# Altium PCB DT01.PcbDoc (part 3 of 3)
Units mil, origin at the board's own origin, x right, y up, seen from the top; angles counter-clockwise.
Board outline 2134.7 x 2226.1 mil, 2 copper layers (Top Layer, Bottom Layer), stack 57.918 mil thick; 95 components, 87 nets, 468 pads, 300 vias.
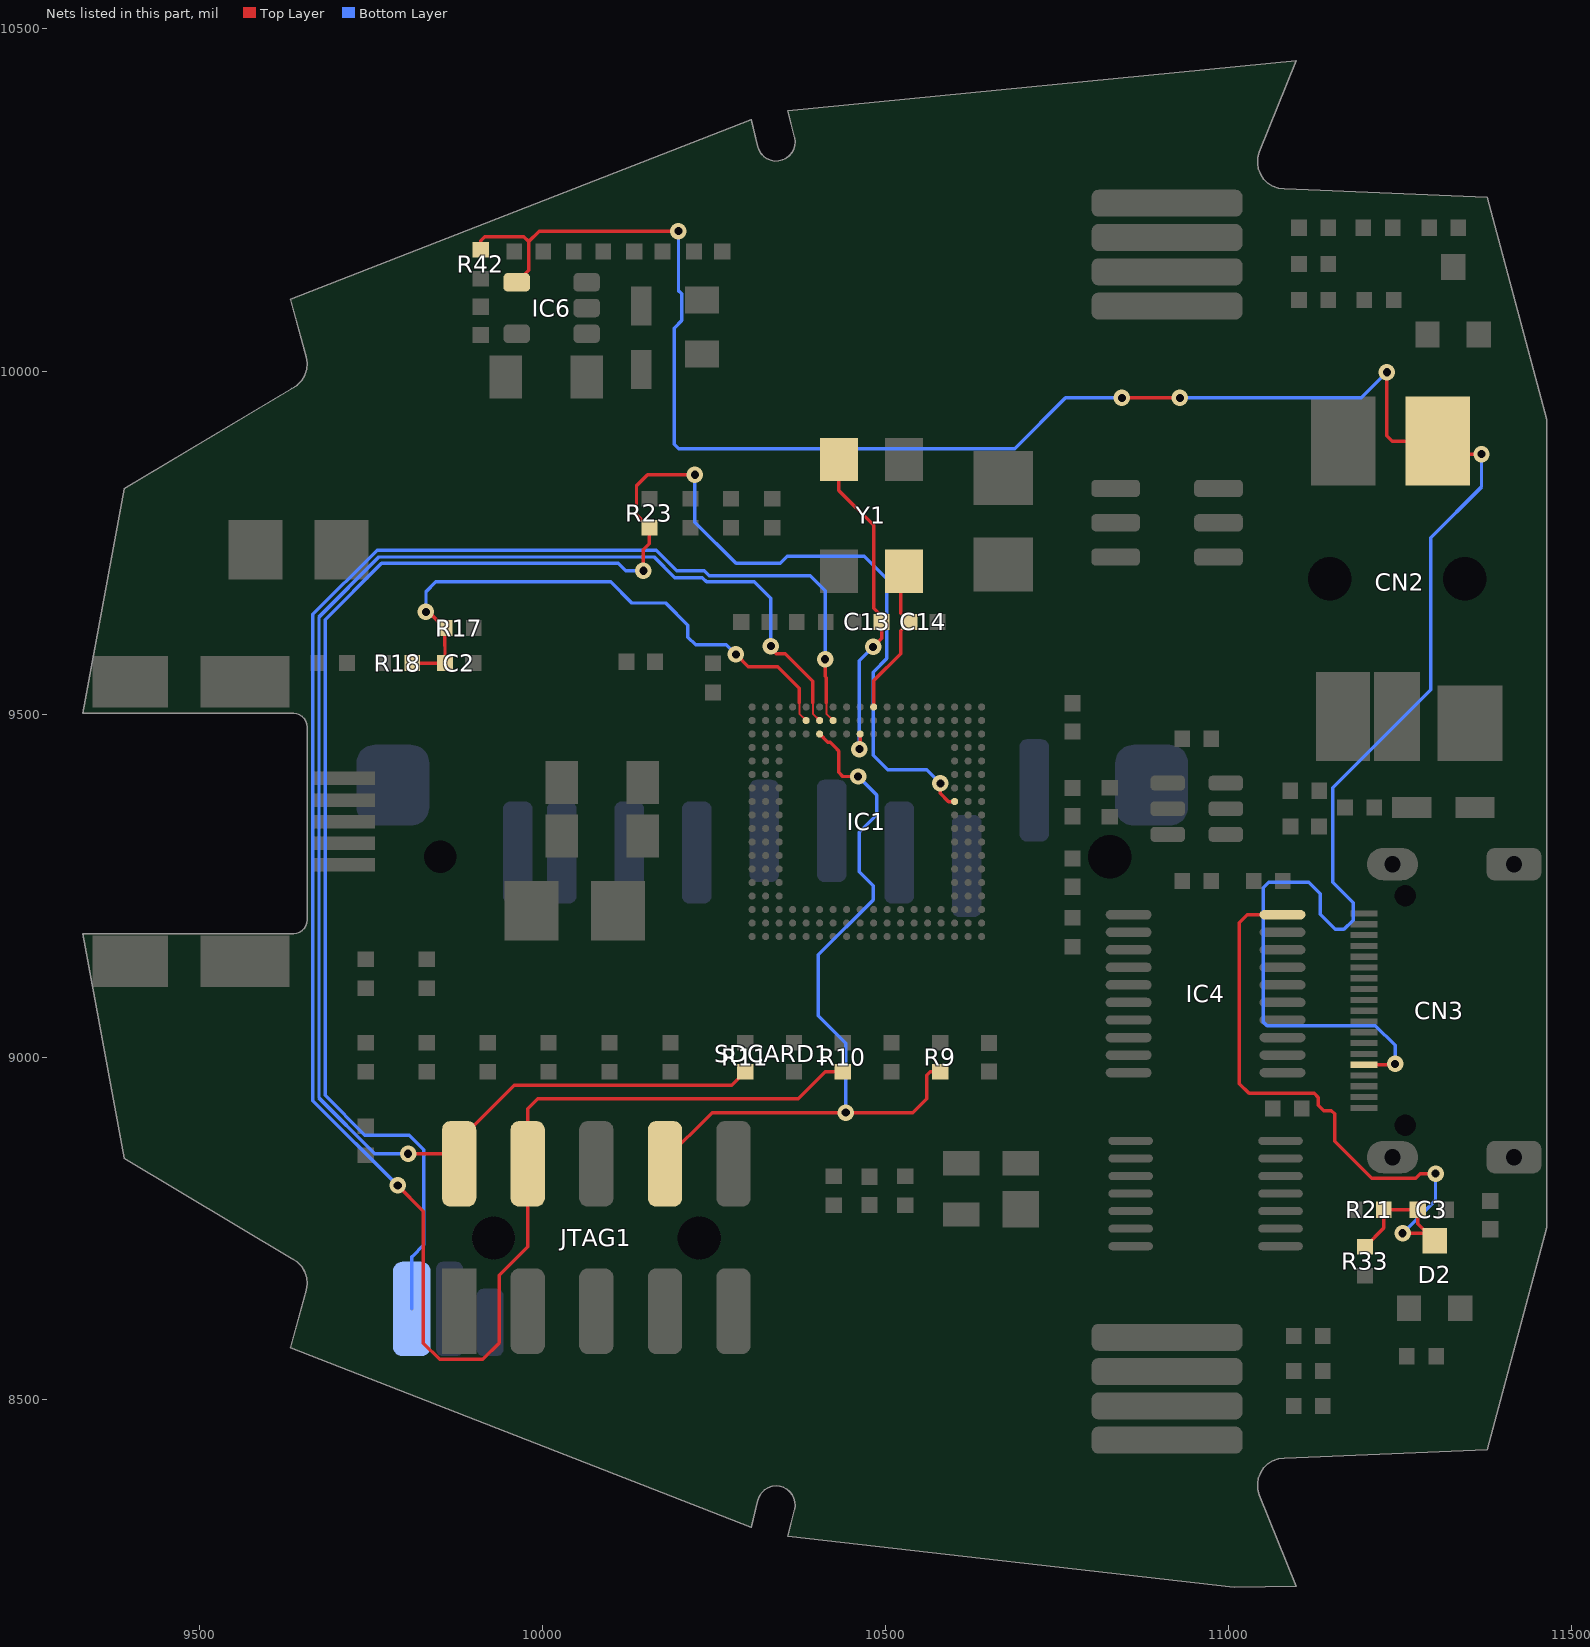
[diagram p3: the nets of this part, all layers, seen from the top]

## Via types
v1: diameter 24, hole 11.81, Top Layer to Bottom Layer, tented both sides, 295 vias
v2: diameter 24.02, hole 11.81, Top Layer to Bottom Layer, tented both sides, 5 vias

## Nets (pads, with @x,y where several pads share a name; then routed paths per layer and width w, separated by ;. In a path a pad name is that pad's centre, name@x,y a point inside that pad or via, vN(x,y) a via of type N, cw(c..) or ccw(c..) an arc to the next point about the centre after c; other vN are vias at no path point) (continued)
TDO: IC1.U13 JTAG1.2 R11.1 | length 2361.9
  Top Layer w3: 10394.06,9516.79 10394.06,9500.5 IC1.U13@10403.95,9490.61
  Top Layer w5: v1(9804.01,8859.02) JTAG1.2@9873.01,8859.02 ; JTAG1.2@9878.38,8844.21 9878.38,8878.67 9958.73,8959.02 10276.11,8959.02 R11.1@10295.6,8978.5 R11.1@10293.01,8978.5 ; v1@10333.01,9596.02 10341.01,9588.02 10354.01,9588.02 10394.06,9547.97 10394.06,9516.79
  Bottom Layer w5: v1(9804.01,8859.02) 9755.25,8859.02 9674,8940.26 9674,9641.59 9761.43,9729.02 10163.01,9729.02 10193.01,9699.02 10233.01,9699.02 10239.02,9693 10308.77,9693 10333.01,9668.76 v1(10333.01,9599.02)
TMS: IC1.U12 JTAG1.4 R10.1 | length 3104.8
  Top Layer w3: 10413.74,9516.79 10413.74,9500.5 IC1.U12@10423.63,9490.61
  Top Layer w5: v1(9788.83,8812.7) 9826.22,8775.31 9826.22,8582.63 9849.84,8559.02 9913.01,8559.02 9937.01,8583.02 9937.01,8682.02 9978.38,8723.4 JTAG1.4@9978.38,8844.21 9978.38,8924.4 9993.01,8939.02 10373.01,8939.02 10412.49,8978.5 R10.1@10437.79,8978.5 ; v1(10412.01,9580.02) 10412.01,9554.87 10413.74,9553.13 10413.74,9516.79
  Bottom Layer w5: v1(9788.83,8812.7) 9665,8936.54 9665,9645.32 9758.7,9739.02 10165.73,9739.02 10195.73,9709.02 10235.73,9709.02 10242.75,9702 10390.02,9702 10412.01,9680.02 v1(10412.01,9580.02)
TPS: C3.1 D2.3 IC4.20 R21.1 R33.1 | length 991.2
  Top Layer w5: IC4.20@11078.92,9207.48 11027.48,9207.48 11016,9196 11016,8961 11030,8947 11125,8947 11131,8941 11131,8929.65 11139,8921.65 11150.22,8921.65 11154.88,8917 11154.88,8877.12 11208.92,8823.08 11273,8823.08 11279.92,8830 v1(11302,8830) ; R33.1@11199.29,8723.57 11226.37,8750.66 R21.1@11226.37,8777.18 C3.1@11276.03,8777.18 11276.03,8756.71 D2.3@11289.75,8743 ; v1(11254,8743) D2.3@11289.75,8743 ; D2.3@11300.73,8732.02 D2.3@11289.75,8743
  Bottom Layer w5: v1(11254,8743) 11302,8791 v1(11302,8830)
TRST: IC1.T13 JTAG1.8 R9.1 | length 1153.3
  Top Layer w5: JTAG1.8@10178.38,8844.21 10178.38,8850.18 10247.22,8919.02 v1(10442.01,8919.02) 10540.01,8919.02 10560.01,8939.02 10560.01,8973.5 10565.01,8978.5 R9.1@10579.97,8978.5 ; IC1.T13@10403.01,9469.02 10403.95,9469.02 IC1.T13@10403.95,9470.92 10415.85,9459.02 10419.17,9459.02 10425.19,9453 10432.01,9446.18 10432.01,9437.02 10432,9415 10437.98,9409.02 v1(10460.01,9409.02)
  Bottom Layer w5: v1(10442.01,8919.02) 10442.01,9020.29 10402.01,9060.29 10402.01,9148.94 10482.01,9228.94 10482.01,9250.02 10462.01,9270.02 10462.01,9328.02 10487.01,9353.02 10487.01,9382.02 v1(10460.01,9409.02)
VPP_ON: CN2.4 CN3.15 IC6.4 R42.2 | length 3470.2
  Top Layer w5: R42.2@9910.37,10177.07 R42.2@9909.87,10177.06 9909.87,10190.31 9915.77,10196.21 9972.82,10196.21 9980.01,10189.02 ; IC6.4@9962.36,10129.53 9980.01,10147.18 9980.01,10189.02 ; v1(10198.18,10204.22) 9995.21,10204.22 9980.01,10189.02 ; v1(10844.66,9961.03) v1(10929.29,9961.03) ; CN3.15@11197.86,8988.84 11227.01,8988.84 11227.01,8989.02 11242.01,8989.02 v1(11243.01,8990.02) ; v1(11231.01,9998.42) 11231.01,9905.93 11238.81,9898.13 CN2.4@11305.14,9898.13 11324.25,9879.02 v1(11369.01,9879.02)
  Bottom Layer w5: v1(10198.18,10204.22) 10198.18,10117.49 10203.1,10112.57 10203.1,10073.9 10192.01,10062.81 10192.01,9893.34 10198.33,9887.02 10688.42,9887.02 10762.43,9961.03 v1(10844.66,9961.03) ; v1(10929.29,9961.03) 11193.61,9961.03 v1(11231.01,9998.42) ; v1(11243.01,8990.02) 11243.01,9016.93 11214.16,9045.77 11056.23,9045.77 11051,9051 11051,9247 11059,9255 11117,9255 11134,9238 11134,9208 11156,9186 11168.59,9186 11182.01,9199.42 11182.01,9225 11152.01,9255 11152.01,9392.56 11295.19,9535.75 11295.19,9757.32 11369.01,9831.14 v1(11369.01,9879.02)
VUSB: C2.2 IC1.U14 R17.1 R18.1 | length 841.7
  Top Layer w3: 10374.37,9516.79 10374.37,9500.5 IC1.U14@10384.26,9490.61
  Top Layer w5: R18.1@9810.02,9574.34 C2.2@9857.71,9574.34 9857.71,9599.02 9857.2,9599.53 R17.1@9857.2,9625.51 9833.69,9649.02 v1(9830.01,9649.02) ; v1(10282.01,9587.02) 10300.01,9569.02 10343.01,9569.02 10374.37,9537.65 10374.37,9516.79
  Bottom Layer w5: v1(9830.01,9649.02) 9830.01,9678.47 9844.55,9693.02 10099.24,9693.02 10130.24,9662.02 10179.67,9662.02 10212,9629.69 10212,9612 10223.11,9600.89 10268.14,9600.89 v1(10282.01,9587.02)
WP_DET: IC1.L3 R23.1 SDCARD1.SW2 | length 2652.9
  Top Layer w5: v1(10147.01,9709.02) 10147.01,9739.63 10155.87,9748.5 R23.1@10155.87,9771.61 10137.01,9790.47 10137.01,9833.02 10153.01,9849.02 v1(10222.01,9849.02) ; v1(10580.01,9399.02) 10580.01,9384.37 10591.88,9372.5 IC1.L3@10600.8,9372.5
  Bottom Layer w5: SDCARD1.SW2@9809.33,8632.63 9809.33,8709.02 9810.01,8709.02 9827.01,8726.02 9827.01,8865.02 9805.86,8886.17 9740.83,8886.17 9683,8943.99 9683,9637.86 9765.15,9720.02 10110.42,9720.02 10121.42,9709.02 v1(10147.01,9709.02) ; v1(10222.01,9849.02) 10222.01,9780.02 10282.02,9720 10346.59,9720 10356.61,9730.02 10469.28,9730.02 10502.01,9697.29 10502.01,9581.02 10482.01,9561.02 10482.01,9440.02 10503.01,9419.02 10560.01,9419.02 v1(10580.01,9399.02)
XTALI: C13.1 IC1.T10 Y1.1 | length 486.5
  Top Layer w5: Y1.1@10432.11,9869.02 Y1.1@10432.1,9871.33 10432.1,9825.96 10483.01,9775.06 10483.01,9654.36 C13.1@10498.69,9638.68 ; v1(10462.01,9449.02) 10462.01,9457.22 10463,9458.22 IC1.T10@10463,9469.02 ; IC1.T10@10462.01,9469.02 IC1.T10@10463,9469.02 ; v1(10482.01,9598.02) 10494.37,9610.38 C13.1@10494.37,9634.36 ; IC1.T10@10463,9469.02 IC1.T10@10463,9470.92 IC1.T10@10463,9469.02
  Bottom Layer w5: v1(10462.01,9449.02) 10462.01,9578.02 v1(10482.01,9598.02)
XTALO: C14.1 IC1.V9 Y1.3 | length 223.8
  Top Layer w5: IC1.V9@10482.69,9510.29 10483.01,9510.29 10483.01,9549.02 10522.01,9588.02 10522.01,9621.66 C14.1@10534.7,9634.36 ; Y1.3@10527.1,9708.33 10526.42,9708.33 10522.01,9703.92 10522.01,9647.04 C14.1@10532.02,9637.03
pads on no net: CN2.MH1 CN2.MH2 CN3.16 CN3.17 CN3.19 CN3.MH5 CN3.MH6 D1.3 IC1.A8 IC1.A9 IC1.A10 IC1.A11 IC1.A12 IC1.A13 IC1.A14 IC1.A17 IC1.A18 IC1.B3 IC1.B9 IC1.B10 IC1.B11 IC1.B12 IC1.B13 IC1.B14 IC1.B15 IC1.B16 IC1.B17 IC1.B18 IC1.C1 IC1.C2 IC1.C3 IC1.C9 IC1.C10 IC1.C11 IC1.C12 IC1.C13 IC1.C14 IC1.C15 IC1.C16 IC1.C17 IC1.C18 IC1.D1 IC1.D2 IC1.D3 IC1.D16 IC1.D17 IC1.D18 IC1.E2 IC1.E3 IC1.E16 IC1.E17 IC1.E18 IC1.F2 IC1.F3 IC1.F16 IC1.F17 IC1.F18 IC1.G2 IC1.G16 IC1.G17 IC1.G18 IC1.H17 IC1.K1 IC1.K2 IC1.K16 IC1.K17 IC1.L2 IC1.M1 IC1.M2 IC1.M3 IC1.N1 IC1.N2 IC1.N3 IC1.P3 IC1.R3 IC1.T1 IC1.T2 IC1.T3 IC1.T4 IC1.T6 IC1.T7 IC1.T8 IC1.U1 IC1.U2 IC1.U5 IC1.U6 IC1.U7 IC1.V1 IC2.3 IC2.5 IC2.6 SDCARD1.MH3 SDCARD1.MH4
copper on no net: | length 12322.3
  Top Layer w5: 13672.98,13929.05 13672.98,14024.05 14592.98,14024.05 14592.98,13929.05 13672.98,13929.05
  Top Layer w10: 6107.15,10595.13 6107.15,11057.18 6817.15,11057.18 6817.15,10595.13 6107.15,10595.13
  Top Layer w40: 10738.55,8378.48 10508.24,8378.48 cw(c10508.24,8516.27) 10508.24,8654.07 10738.55,8654.07 ; 10738.55,10032.02 10508.24,10032.02 cw(c10508.24,10169.82) 10508.24,10307.61 10738.55,10307.61
  Bottom Layer w5: 13672.98,13834.05 13672.98,13929.05 14592.98,13929.05 14592.98,13834.05 13672.98,13834.05
  Bottom Layer w10: 6107.15,10595.13 6107.15,11057.18 6817.15,11057.18 6817.15,10595.13 6107.15,10595.13
  Bottom Layer w40: 10738.55,8378.48 10508.24,8378.48 cw(c10508.24,8516.27) 10508.24,8654.07 10738.55,8654.07 ; 10738.55,10032.02 10508.24,10032.02 cw(c10508.24,10169.82) 10508.24,10307.61 10738.55,10307.61
  other v2: 10830.98,9882.99 10932.01,9882.99 10820,10045 11197.01,10052.99

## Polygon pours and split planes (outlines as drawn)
GND on Top Layer "TOPGND" (solid, remove dead copper, pour order 1000): 11097.83,8230.7 11044.32,8363.83 11042.45,8378.76 11053.27,8408.28 11080.68,8417.88 11228.42,8421.07 11376.58,8429.84 11425.22,8590.32 11463.13,8754.11 11463.13,9931.98 11432.11,10071.24 11376.58,10256.24 11226.46,10265.09 11080.68,10268.2 11065.08,10270.99 11053.27,10278.86 11043.43,10293.62 11041.46,10307.4 11044.32,10322.26 11097.83,10455.38 10842.7,10453.03 10592.76,10426.46 10471.73,10405.8 10356.73,10382.38 10366.39,10343.02 10367.42,10331.02 10364.47,10323.14 10352.66,10311.34 10335.94,10308.38 10319.21,10317.24 10312.86,10329.88 10303.15,10369.43 10081.08,10304.45 9861.65,10218.84 9631.51,10107.14 9654.65,10023.4 9656.98,10015.15 9655.01,10003.34 9650.09,9989.57 9633.7,9977.41 9512.33,9916.75 9388.86,9831.12 9351.94,9676.66 9328.42,9503.48 9636.2,9503.48 9654.02,9489.7 9655.89,9202.3 9636.2,9182.61 9328.42,9182.61 9349.97,9017.38 9388.86,8854.97 9510.36,8775.31 9633.7,8708.68 9644.18,8701.51 9651.07,8693.64 9655.01,8683.8 9655.99,8674.94 9654.65,8662.69 9631.51,8578.94 9799.66,8493.89 9916.75,8444.69 10041.72,8394.5 10250.33,8329.56 10303.15,8316.66 10312.86,8356.21 10317.24,8364.98 10321.18,8370.89 10329.05,8375.81 10335.94,8377.78 10344.79,8376.79 10351.68,8374.82 10359.55,8369.9 10362.5,8365.97 10366.44,8359.08 10367.42,8352.19 10366.39,8343.07 10356.73,8303.7 10547.5,8266.58 10673.45,8248.87 10751.18,8241 10825.97,8235.1 10899.77,8231.16 10941.1,8230.18 11009.98,8230.18 11023.75,8229.19 11036.54,8230.18 11062.13,8231.16
GND on Bottom Layer "BOTGND" (solid, remove dead copper, pour order 1001): 11097.83,8230.7 11044.32,8363.83 11042.45,8378.76 11053.27,8408.28 11080.68,8417.88 11228.42,8421.07 11376.58,8429.84 11425.22,8590.32 11463.13,8754.11 11463.13,9931.98 11432.11,10071.24 11376.58,10256.24 11226.46,10265.09 11080.68,10268.2 11065.08,10270.99 11053.27,10278.86 11043.43,10293.62 11041.46,10307.4 11044.32,10322.26 11097.83,10455.38 10842.7,10453.03 10592.76,10426.46 10471.73,10405.8 10356.73,10382.38 10366.39,10343.02 10367.42,10331.02 10364.47,10323.14 10352.66,10311.34 10335.94,10308.38 10319.21,10317.24 10312.86,10329.88 10303.15,10369.43 10081.08,10304.45 9861.65,10218.84 9631.51,10107.14 9654.65,10023.4 9656.98,10015.15 9655.01,10003.34 9650.09,9989.57 9633.7,9977.41 9512.33,9916.75 9388.86,9831.12 9351.94,9676.66 9328.42,9503.48 9636.2,9503.48 9654.02,9489.7 9655.89,9202.3 9636.2,9182.61 9328.42,9182.61 9349.97,9017.38 9388.86,8854.97 9510.36,8775.31 9633.7,8708.68 9644.18,8701.51 9651.07,8693.64 9655.01,8683.8 9655.99,8674.94 9654.65,8662.69 9631.51,8578.94 9799.66,8493.89 9916.75,8444.69 10041.72,8394.5 10250.33,8329.56 10303.15,8316.66 10312.86,8356.21 10317.24,8364.98 10321.18,8370.89 10329.05,8375.81 10335.94,8377.78 10344.79,8376.79 10351.68,8374.82 10359.55,8369.9 10362.5,8365.97 10366.44,8359.08 10367.42,8352.19 10366.39,8343.07 10356.73,8303.7 10547.5,8266.58 10673.45,8248.87 10751.18,8241 10825.97,8235.1 10899.77,8231.16 10941.1,8230.18 11009.98,8230.18 11023.75,8229.19 11036.54,8230.18 11062.13,8231.16
no net on Keep-Out Layer (solid): 10738.55,10307.61 10509.06,10307.61 10499.2,10307.5 10488.4,10306.4 10481.5,10304.7 10474.7,10303.5 10463.7,10300.3 10451.3,10295.4 10441.4,10290.7 10428.3,10281.8 10417.61,10273.94 10409.1,10265.8 10401.9,10257.4 10394,10246.7 10387.3,10235.4 10381,10222.8 10377,10211.8 10372.8,10195.3 10371.4,10183.9 10370.5,10172.6 10371.1,10154.4 10374,10138.3 10377,10126.7 10382.5,10113.2 10387.9,10102.9 10398.5,10085.8 10412.3,10070.8 10426.5,10059.1 10435.2,10052.9 10446.7,10046.5 10463.6,10039.5 10473.8,10036.5 10487,10033.6 10491.9,10033 10495.4,10032.6 10501.1,10032.1 10508.24,10032.02 10738.55,10032.02 10741.1,10032.2 10743,10032.5 10745.4,10033.3 10747.1,10034 10748.8,10034.9 10750.3,10035.8 10751.2,10036.8 10752.5,10037.8 10754.6,10040.3 10756,10042.3 10757.1,10045 10757.8,10047.6 10758.2,10050 10758.24,10051.71 10758.24,10287.93 10757.8,10291.7 10757.2,10294.6 10755.4,10298.3 10753.15,10301.5 10750.9,10303.5 10748,10305.2 10744,10307
no net on Keep-Out Layer (solid): 10738.55,8654.07 10509.06,8654.07 10499.2,8653.96 10488.4,8652.86 10481.5,8651.16 10474.7,8649.96 10463.7,8646.76 10451.3,8641.86 10441.4,8637.16 10428.3,8628.26 10417.61,8620.4 10409.1,8612.26 10401.9,8603.86 10394,8593.16 10387.3,8581.86 10381,8569.26 10377,8558.26 10372.8,8541.76 10371.4,8530.36 10370.5,8519.06 10371.1,8500.86 10374,8484.76 10377,8473.16 10382.5,8459.66 10387.9,8449.36 10398.5,8432.26 10412.3,8417.26 10426.5,8405.56 10435.2,8399.36 10446.7,8392.96 10463.6,8385.96 10473.8,8382.96 10487,8380.06 10491.9,8379.46 10495.4,8379.06 10501.1,8378.56 10508.24,8378.48 10738.55,8378.48 10741.1,8378.66 10743,8378.96 10745.4,8379.76 10747.1,8380.46 10748.8,8381.36 10750.3,8382.26 10751.2,8383.26 10752.5,8384.26 10754.6,8386.76 10756,8388.76 10757.1,8391.46 10757.8,8394.06 10758.2,8396.46 10758.24,8398.16 10758.24,8634.38 10757.8,8638.16 10757.2,8641.06 10755.4,8644.76 10753.15,8647.95 10750.9,8649.96 10748,8651.66 10744,8653.46

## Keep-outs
Keep-Out Layer:
  rectangle: 13672.98,12418.05 13862.98,12513.05
  lines w5: 13672.98,12418.05 13672.98,12513.05 14592.98,12513.05 14592.98,12418.05 13672.98,12418.05
  text "ROUTING KEEPOUT LAYER" at 13932.98,12445.05 h35

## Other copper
Top Layer:
  rectangle net 5V0: 9708,9252 9732,9285
  rectangle: 13672.98,13929.05 13862.98,14024.05
  pour cut-out: 10305.52,9510.29 10640.17,9510.29 10640.17,9175.65 10305.52,9175.65
  text "TOP LAYER" at 13932.98,13956.05 h40
  text "LAYER" at 6337.58,10910.08 h60
  text "TOP" at 6310.02,10701.42 h120
Bottom Layer:
  rectangle: 13672.98,13834.05 13862.98,13929.05
  text "BOTTOM LAYER" at 13932.98,13861.05 h40
  text "LAYER" at 6337.58,10910.08 h60
  text "BOTTOM" at 6148.6,10705.35 h120
Multi-Layer:
  rectangle: 13672.98,13008.05 13862.98,13103.05
  lines w5: 13672.98,13008.05 13672.98,13103.05 14592.98,13103.05 14592.98,13008.05 13672.98,13008.05
  text "MULTILAYER" at 13932.98,13035.05 h40
  text "OF" at 22030.96,501.86 h80
  text "1" at 21835.88,501.31 h120
  text "1" at 22270.88,501.31 h120

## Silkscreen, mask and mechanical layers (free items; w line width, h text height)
Top Overlay:
  drawing of 466 lines, arcs and shapes, not listed
  text "TOP OVERLAY" at 13932.98,14192.05 h40
  text "K" at 10300.56,10129.75 h30
  text "FLAT" at 10898,10013 h40
  text "+" at 9767,9803 h80
  text "DS2406" at 10916.8,9722.6 h35 r90
  text "+" at 10739,9615 h80
  text "STX-2550-5N" at 11105.91,9609.87 h35 r90
  text "K" at 11401,9350 h30
  text "LPC288x" at 10260,9263 h40 r90
  text "+" at 9889,9100 h80
  text "74CBT3345" at 10992.76,8974.48 h28 r90
  text "INTERFACE" at 11368,8946 h50 r90
  text "G3168-05000102-00" at 11414.8,8927.2 h35 r90
  text "TARGET JTAG" at 11321.57,8915.39 h50 r90
  text "HC04" at 10996,8736 h34 r90
  text "FLAT" at 10877,8360 h40
Bottom Overlay:
  drawing of 1101 lines, arcs and shapes, not listed
  text "BOTTOM LEGEND" at 13932.98,13625.05 h40
  text "SD CARD" at 10491,9902 h80
  text "MANUFACTURE DATE:" at 11291,9740 h28 r90
  text "REVISION No:" at 10588,9732.29 h50
  text "DT01.02" at 11198,9655 h60 r90
  text "SVN 7266" at 10591,9640.36 h95
  text "MACHINE ID:" at 10588,9542.58 h50
  text ".ComputerName" at 10591,9453 h95
  text "DT01.02" at 11369.67,9244.43 h90 r90
  text "Developer" at 11426.67,9244.43 h60 r90
  text "Tool" at 11491.67,9244.43 h60 r90
  text "AD BUILD No:" at 10588,9109.58 h50
  text "COMPLIANCE" at 9755.08,9029.05 h52
  text ".Application_BuildNumber" at 10591,9020 h95
  text "IPC-A-600G" at 9712.08,8961.05 h30
  text "IPC-6012D" at 9712.08,8903.05 h30
Top Paste:
  rectangle: 13672.98,14283.05 13862.98,14378.05
  lines w5: 13672.98,14283.05 13672.98,14378.05 14592.98,14378.05 14592.98,14283.05 13672.98,14283.05
  text "TOP PASTE" at 13932.98,14310.05 h40
Bottom Paste:
  rectangle: 13672.98,13480.05 13862.98,13575.05
  lines w5: 13672.98,13480.05 13672.98,13575.05 14592.98,13575.05 14592.98,13480.05 13672.98,13480.05
  text "BOTTOM PASTE" at 13932.98,13507.05 h40
Top Solder:
  rectangle: 13672.98,14047.05 13862.98,14142.05
  lines w5: 13672.98,14047.05 14592.98,14047.05 14592.98,14142.05 13672.98,14142.05 13672.98,14047.05
  lines w40: 10738.55,8378.48 10508.24,8378.48 cw(c10508.24,8516.27) 10508.24,8654.07 10738.55,8654.07 ; 10738.55,10032.02 10508.24,10032.02 cw(c10508.24,10169.82) 10508.24,10307.61 10738.55,10307.61
  lines w60: 9622,9182.61 9366.52,9182.61 9328.42,9182.61 ccw(c11116.51,9343.04) 9388.86,8854.97 ccw(c10303.51,10107.8) 9633.7,8708.68 cw(c9616.7,8673.17) 9654.65,8662.69 9631.51,8578.94 ccw(c11007.41,11111.18) 10303.15,8316.66 10312.86,8356.21 cw(c10339.63,8349.64) 10366.39,8343.07 10356.73,8303.7 ccw(c11007.41,11111.18) 11097.83,8230.7 11044.32,8363.83 cw(c11080.85,8378.51) 11080.68,8417.88 ccw(c11063.75,12502.73) 11376.58,8429.84 ccw(c8605.87,9343.04) 11463.13,8754.11 11463.13,9287.93 11463.13,9520.21 11463.13,9697.37 11463.13,9931.98 ccw(c8605.87,9343.04) 11376.58,10256.24 ccw(c11063.75,6183.36) 11080.68,10268.2 cw(c11080.85,10307.57) 11044.32,10322.26 11097.83,10455.38 ccw(c11007.41,7574.91) 10356.73,10382.38 10366.39,10343.02 cw(c10339.63,10336.45) 10312.86,10329.88 10303.15,10369.43 ccw(c11007.41,7574.91) 9631.51,10107.14 9654.65,10023.4 cw(c9616.7,10012.92) 9633.7,9977.41 ccw(c10303.51,8578.29) 9388.86,9831.12 ccw(c11116.51,9343.04) 9328.42,9503.48 9366.52,9503.48 9622,9503.48
  text "TOP SOLDER MASK" at 13932.98,14074.05 h40
Bottom Solder:
  rectangle: 13672.98,13716.05 13862.98,13811.05
  lines w5: 13672.98,13716.05 13672.98,13811.05 14592.98,13811.05 14592.98,13716.05 13672.98,13716.05
  lines w40: 10738.55,8378.48 10508.24,8378.48 cw(c10508.24,8516.27) 10508.24,8654.07 10738.55,8654.07 ; 10738.55,10032.02 10508.24,10032.02 cw(c10508.24,10169.82) 10508.24,10307.61 10738.55,10307.61
  lines w60: 9622,9182.61 9366.52,9182.61 9328.42,9182.61 ccw(c11116.51,9343.04) 9388.86,8854.97 ccw(c10303.51,10107.8) 9633.7,8708.68 cw(c9616.7,8673.17) 9654.65,8662.69 9631.51,8578.94 ccw(c11007.41,11111.18) 10303.15,8316.66 10312.86,8356.21 cw(c10339.63,8349.64) 10366.39,8343.07 10356.73,8303.7 ccw(c11007.41,11111.18) 11097.83,8230.7 11044.32,8363.83 cw(c11080.85,8378.51) 11080.68,8417.88 ccw(c11063.75,12502.73) 11376.58,8429.84 ccw(c8605.87,9343.04) 11463.13,8754.11 11463.13,9287.93 11463.13,9520.21 11463.13,9697.37 11463.13,9931.98 ccw(c8605.87,9343.04) 11376.58,10256.24 ccw(c11063.75,6183.36) 11080.68,10268.2 cw(c11080.85,10307.57) 11044.32,10322.26 11097.83,10455.38 ccw(c11007.41,7574.91) 10356.73,10382.38 10366.39,10343.02 cw(c10339.63,10336.45) 10312.86,10329.88 10303.15,10369.43 ccw(c11007.41,7574.91) 9631.51,10107.14 9654.65,10023.4 cw(c9616.7,10012.92) 9633.7,9977.41 ccw(c10303.51,8578.29) 9388.86,9831.12 ccw(c11116.51,9343.04) 9328.42,9503.48 9366.52,9503.48 9622,9503.48
  text "BOTTOM SOLDER MASK" at 13932.98,13743.05 h40
Drill Guide:
  rectangle: 13672.98,13362.05 13862.98,13457.05
  lines w5: 13672.98,13362.05 14592.98,13362.05 14592.98,13457.05 13672.98,13457.05 13672.98,13362.05
  lines w10: 9329.39,9180.02 9637.16,9180.02 9641.54,9180.52 9645.7,9181.97 9649.44,9184.32 9652.55,9187.43 9654.9,9191.17 9656.35,9195.33 9656.85,9199.71 9656.85,9481.2 9656.35,9485.58 9654.9,9489.74 9652.55,9493.48 9649.44,9496.59 9645.7,9498.94 9641.54,9500.39 9637.16,9500.89 9329.39,9500.89 9389.82,9828.53 9634.66,9974.82 9642.38,9979.68 9648.77,9986.2 9653.49,9994.01 9656.28,10002.7 9657,10011.79 9655.61,10020.81 9632.47,10104.55 10304.11,10366.84 10313.82,10327.29 10315.77,10321.87 10318.81,10316.97 10322.8,10312.81 10327.56,10309.57 10332.89,10307.39 10338.56,10306.37 10344.32,10306.55 10349.92,10307.93 10355.11,10310.43 10359.66,10313.96 10363.38,10318.36 10366.1,10323.44 10367.71,10328.97 10368.13,10334.72 10367.35,10340.43 10357.69,10379.8 11098.79,10452.79 11045.28,10319.67 11042.98,10311.48 11042.49,10302.98 11043.84,10294.58 11046.96,10286.67 11051.71,10279.61 11057.86,10273.73 11065.14,10269.32 11073.19,10266.57 11081.64,10265.62 11377.54,10253.65 11464.09,9929.39 11464.09,8751.52 11377.54,8427.26 11081.64,8415.29 11073.19,8414.34 11065.14,8411.59 11057.86,8407.18 11051.71,8401.3 11046.96,8394.24 11043.84,8386.33 11042.49,8377.93 11042.98,8369.43 11045.28,8361.24 11098.79,8228.12 11008.37,8226.7 10357.69,8301.11 10367.35,8340.48 10368.12,8345.97 10367.79,8351.49 10366.35,8356.84 10363.87,8361.79 10360.45,8366.15 10356.24,8369.74 10351.38,8372.41 10346.1,8374.06 10340.59,8374.61 10334.53,8373.94 10328.76,8371.95 10323.58,8368.74 10319.23,8364.47 10315.92,8359.35 10313.82,8353.62 10304.11,8314.07 9632.47,8576.36 9655.61,8660.1 9657,8669.12 9656.28,8678.21 9653.49,8686.9 9648.77,8694.71 9642.38,8701.23 9634.66,8706.09 9389.82,8852.38 9329.39,9180.02
  lines w66.93: 10508.18,8412.67 cw(c10508.25,8516.25) 10508.25,8619.83 10724.04,8619.87 10724.04,8412.67 10508.25,8412.67 ; 10508.18,10066.21 cw(c10508.25,10169.8) 10508.25,10273.38 10724.04,10273.42 10724.04,10066.21 10508.25,10066.21
  text "DRILL GUIDE (SLOTS)" at 13932.98,13389.05 h40
Mechanical 1:
  rectangle: 13672.98,13126.05 13862.98,13221.05
  rectangle: 13584.61,7299.25 15028.78,7361.12
  rectangle: 13584.61,7537.39 15028.78,7599.25
  lines w0.39: 9328.42,9182.61 ccw(c11116.51,9343.04) 9388.86,8854.97 ccw(c10303.51,10107.8) 9633.7,8708.68 cw(c9616.7,8673.17) 9654.65,8662.69 9631.51,8578.94 ccw(c11007.41,11111.18) 10303.15,8316.66 10312.86,8356.21 cw(c10339.63,8349.64) 10366.39,8343.07 10356.73,8303.7 ccw(c11007.41,11111.18) 11097.83,8230.7 11044.32,8363.83 cw(c11080.85,8378.51) 11080.68,8417.88 ccw(c11063.75,12502.73) 11376.58,8429.84 ccw(c8605.87,9343.04) 11463.13,8754.11 11463.13,9287.93 11463.13,9520.21 11463.13,9697.37 11463.13,9931.98 ccw(c8605.87,9343.04) 11376.58,10256.24 ccw(c11063.75,6183.36) 11080.68,10268.2 cw(c11080.85,10307.57) 11044.32,10322.26 11097.83,10455.38 ccw(c11007.41,7574.91) 10356.73,10382.38 10366.39,10343.02 cw(c10339.63,10336.45) 10312.86,10329.88 10303.15,10369.43 ccw(c11007.41,7574.91) 9631.51,10107.14 9654.65,10023.4 cw(c9616.7,10012.92) 9633.7,9977.41 ccw(c10303.51,8578.29) 9388.86,9831.12 ccw(c11116.51,9343.04) 9328.42,9503.48 9366.52,9503.48 9535.81,9503.48 9636.2,9503.48 cw(c9636.2,9483.79) 9655.89,9483.79 9655.89,9202.3 cw(c9636.2,9202.3) 9636.2,9182.61 9535.81,9182.61 9366.52,9182.61 9328.42,9182.61 ; 10508.24,8378.48 cw(c10508.24,8516.27) 10508.24,8654.07 10738.55,8654.07 cw(c10738.55,8634.38) 10758.24,8634.38 10758.24,8601.11 10758.24,8398.16 cw(c10738.55,8398.16) 10738.55,8378.48 10508.24,8378.48 ; 10508.24,10032.02 cw(c10508.24,10169.82) 10508.24,10307.61 10738.55,10307.61 cw(c10738.55,10287.93) 10758.24,10287.93 10758.24,10084.97 10758.24,10051.71 cw(c10738.55,10051.71) 10738.55,10032.02 10508.24,10032.02
  lines w5: 13672.98,13126.05 14592.98,13126.05 14592.98,13221.05 13672.98,13221.05 13672.98,13126.05
  lines w10: 13584.61,7299.25 13584.61,7599.25 15028.78,7599.25 15028.78,7299.25 13584.61,7299.25
  lines w12.01: 11376.58,8429.84 13584.63,7453.88
  text "BOARD OUTLINE" at 13932.98,13153.05 h40
  text "PCB BOARD OUTLINE" at 13745.65,7405.38 h80
Mechanical 3:
  rectangle: 13672.98,12890.05 13862.98,12985.05
  lines w5: 13672.98,12890.05 13672.98,12985.05 14592.98,12985.05 14592.98,12890.05 13672.98,12890.05
  lines w6: 6164.15,9211.91 6774.15,9211.91 6774.15,9461.91 6164.15,9461.91 6164.15,9211.91
  lines w8: 21948,2634 22873,2634
  lines w10: 6823,9270 9357,8957 ; 13762.98,14468.05 14532.98,14468.05 ; 6118.72,8557.91 6828.72,8557.91 6828.72,10001.91 6118.72,10001.91 6118.72,8557.91 ; 13572.98,12331.05 14702.98,12331.05 14702.98,14688.05 13572.98,14688.05 13572.98,12331.05
  lines w15: 6194.15,9801.91 6434.15,9801.91
  text "3 TRACK" at 17927.8,15741.57 h69
  text "24 VIA" at 18492.8,15741.57 h69
  text "3 SPACE" at 18992.8,15741.57 h69
  text "54.22mm" at 19763.55,15733.54 h69
  text "51.45mm" at 20507.64,15733.54 h69
  text "DS" at 19684,14937.36 h69
  text "X" at 19532.96,14935.36 h69
  text "LAYER USAGE" at 13762.98,14496.05 h80
  text "FEED THRU'" at 18968.18,14386.86 h69
  text "TENTED" at 19921,14386.86 h69
  text "X" at 19744,14384.86 h69
  text "X" at 18778.14,14383.36 h69
  text "UNIQUE DRILL" at 18968.18,14189.86 h69
  text "X" at 18778,14185.86 h69
  text "X" at 21405,14012.86 h69
  text "AS SHOWN" at 21555,14012.86 h69
  text "X" at 20335,13817.86 h69
  text "CAD" at 20492,13816.86 h69
  text "1" at 22563.37,13232.05 h69
  text "DT01.02" at 18014.96,13213.86 h69
  text "DEVELOPMENT TOOL 01.02" at 19634.96,13213.86 h69
  text "TECHNICAL DATA" at 13932.98,12917.05 h40
  text "NOTE" at 6190.15,9844.91 h70
  text "DRILL DRAWING" at 18167.43,9824.55 h69
  text "APERTURE TABLES\FILES ARE EMBEDDED" at 19776.43,9824.55 h69
  text "1" at 22562.3,9822.33 h69
  text "BOARDS HAVE" at 6190.15,9664.91 h50
  text "PLATED EDGES" at 6190.15,9564.91 h50
  text "TUC-722" at 22372.81,9540 h69
  text "X" at 22182.77,9537 h69
  text "MILL CUTOUTS" at 6224.15,9361.91 h50
  text "1.2mm" at 20000,9353 h69
  text "X" at 19809.96,9350 h69
  text "BEFORE PLATING" at 6200.15,9274.91 h50
  text "X" at 19101.57,9177.84 h68.9
  text "IN A/W ANSI IPC-6012 TYPE 2 CLASS 2" at 19291,9176.5 h69
  text "ALL" at 6392.59,9029.91 h50
  text "X" at 19100,9000.5 h69
  text "IN A/W ANSI IPC-6012 TYPE 2 CLASS 2" at 19291,8999.5 h69
  text "SIDES ARE" at 6274.88,8936.91 h50
  text "PLATED BY" at 6262.15,8846.91 h50
  text "DESIGN" at 6339.15,8756.91 h50
  text "35um (1oz)" at 20492,8643 h69
  text "X" at 20301.96,8640 h69
  text "35um (1oz)" at 20492,8466 h69
  text "X" at 20301.96,8463 h69
  text "35um (1oz)" at 20492,8290 h69
  text "X" at 20301.96,8287 h69
  text "AS SHOWN" at 21614,7917.5 h69
  text "X" at 21420,7916.5 h69
  text "X" at 19105,7622.5 h69
  text "COMPONENT SIDE" at 19291,7622.5 h69
  text "X" at 19105,7446.5 h69
  text "X" at 21930,7446.5 h69
  text "AS SHOWN" at 19291,7444.5 h69
  text "NC_ DRILL FILES" at 22126,7444.5 h69
  text "20um" at 20492,7266.5 h69
  text "X" at 20300,7265.5 h69
  text "AS SHOWN" at 21082.5,6909 h69
  text "X" at 20892.47,6908.36 h69
  text "X" at 20896,6517.5 h69
  text "X" at 21940,6517.5 h69
  text "COMPONENT" at 21082,6515.5 h69
  text "SOLDER" at 22126,6515.5 h69
  text "WHITE" at 19291,6338.5 h69
  text "X" at 19097.76,6335.66 h69
  text "SCREEN PRINT" at 21082,6142.5 h69
  text "X" at 20891.96,6138 h69
  text "BLACK" at 22099.96,5964.36 h69
  text "GLOSS" at 19291,5963 h69
  text "X" at 19100.96,5960 h69
  text "X" at 21935.96,5960 h69
  text "3um IMMERSION GOLD SMOBC (SOLDER MASK OVER BARE COPPER)" at 19291,5217.5 h69
  text "X" at 19102.05,5212.18 h69
  text "X" at 19100,4667.5 h69
  text "CUT AND TRIM ACCORDING TO LAYER MECHANICAL 1 (BOARD OUTLINE)" at 19291,4665.5 h69
  text "N.C. ROUTE" at 20256,4133 h69
  text "X" at 20065.96,4132.36 h69
  text "X" at 19101.5,3667.5 h69
  text "IN A/W ANSI IPC-A-600F" at 19290.5,3661.5 h69
  text "2" at 21378.5,3661.5 h69
  text "X" at 21227.56,3656.18 h69
  text "NONE" at 19290.5,3011.5 h69
  text "X" at 19099.29,3005.55 h69
  text "2" at 22558,2833.5 h69
  text "X" at 22367.96,2829 h69
  text "PER ORDER" at 22085.96,2661.86 h69
  text "OTHER" at 21633,2654 h69
  text "X" at 21445.75,2645.79 h69
  text "X" at 20641,2481.5 h69
  text "REQUIRED" at 20841,2478.5 h69
  text "2 SIDES" at 20963.71,2300.5 h69
  text "0.65MM" at 22329.66,2298.07 h69
  text "X" at 20769.96,2291.36 h69
  text "LEGEND" at 20964,2124.5 h69
  text "X" at 20773.96,2120 h69
  text "X" at 19930,1946.5 h69
  text "IS09001/AS3901" at 20117,1946.5 h69
  text "X" at 19628.62,1751.5 h69
  text "PER ORDER" at 19825.62,1750.5 h69
Mechanical 6:
  drawing of 2027 lines, arcs and shapes, not listed
  text "DESIGN INFORMATION" at 17933,16019.36 h79
  text "PRODUCT FAMILY" at 1046.66,15989.53 h118.11
  text "DRAWING ID/MODEL." at 3940.36,15989.53 h118.11
  text "(REFER ALSO PROFILING INFORMATION)" at 20450,15870.36 h69
  text "BOARD TECHNOLOGY" at 17933,15861.36 h75
  text "BOARD SIZE" at 19764,15861.36 h75
  text "X" at 20382.96,15725.86 h69
  text "(MIN. TRACK / PADS / CLEARANCE" at 17935,15555.36 h69
  text "IN 0.001\" )" at 19706,15555.36 h69
  text "EXTERNAL" at 19987,15435.36 h69
  text "PER IPC-D-275 CLASS 2" at 20539,15435.36 h69
  text "LEVEL C AND IS THE" at 21867,15435.36 h69
  text "MINIMUM ANNULAR RING 0.05MM" at 17935,15434.36 h69
  text "(0.002\")" at 19529,15434.36 h69
  text "MANUFACTURING REGISTRATION" at 17940,15317.36 h69
  text "ALLOWANCE" at 19495,15317.36 h69
  text "CIRCUIT TYPE:" at 17933,14937.36 h75
  text "SS" at 18933.12,14937.36 h69
  text "PTH MULTILAYER" at 20491,14937.36 h69
  text "Number of Layers :" at 21555,14937.36 h69
  text "FINGER CONNECTOR DIM PER:" at 17933,14760.36 h75
  text "AS SHOWN" at 21555,14760.36 h69
  text "No. OFF TOTAL" at 18957,14602.36 h69
  text "BOTH SIDES" at 21555,14583.86 h69
  text "ONE SIDE" at 20492,14582.36 h69
  text "BUILD STATISTICS" at 12517.23,14567.75 h60
  text "BUILD STATISTICS" at 12517.23,14567.75 h60
  text "GENERAL" at 12509.23,14421.75 h40
  text "GENERAL" at 12509.23,14421.75 h40
  text "VIAS:" at 17933,14385.36 h75
  text "BURIED LAYER SEQUENCE" at 20866,14385.36 h69
  text "NONE" at 18428.35,14384.34 h69
  text ".Net_Count" at 12890.23,14338.75 h40
  text ".Net_Count" at 12890.23,14338.75 h40
  text "NETS" at 12512.23,14336.75 h35
  text "NETS" at 12512.23,14336.75 h35
  text ".Component_Count" at 12890.23,14256.75 h40
  text ".Component_Count" at 12890.23,14256.75 h40
  text "COMPONENTS" at 12513.23,14255.75 h35
  text "COMPONENTS" at 12513.23,14255.75 h35
  text "2 SIZES" at 19921,14188.36 h69
  text "BLIND LAYER SEQUENCE" at 20866,14188.36 h69
  text "PRIMITIVES" at 12510.23,14118.75 h40
  text "PRIMITIVES" at 12510.23,14118.75 h40
  text ".Fill_Count" at 12890.23,14034.75 h40
  text ".Fill_Count" at 12890.23,14034.75 h40
  text "FILLS" at 12513.23,14033.75 h35
  text "FILLS" at 12513.23,14033.75 h35
  text "LAYER CONSTRUCTION PER:" at 17933,14011.36 h75
  text "LAMINATION SEQUENCE" at 19744,14011.36 h69
  text ".Track_Count" at 12890.23,13953.75 h40
  text ".Track_Count" at 12890.23,13953.75 h40
  text "TRACKS" at 12513.23,13951.75 h35
  text "TRACKS" at 12513.23,13951.75 h35
  text ".String_Count" at 12890.23,13871.75 h40
  text ".String_Count" at 12890.23,13871.75 h40
  text "STRINGS" at 12513.23,13869.75 h35
  text "STRINGS" at 12513.23,13869.75 h35
  text "NB2.05" at 21428.47,13843.78 h70
  text "FILE NAME:" at 20881.34,13832.08 h69
  text "ARTWORK:" at 17933,13815.36 h75
  text "MANUAL" at 18932.8,13815.36 h69
  text "DIGITISED" at 19685,13815.36 h69
  text ".Arc_Count" at 12890.23,13788.75 h40
  text ".Arc_Count" at 12890.23,13788.75 h40
  text "ARC'S" at 12513.23,13786.75 h35
  text "ARC'S" at 12513.23,13786.75 h35
  text "IMPEDANCE CONTROLLED" at 7382,13741 h75
  text "GERBER SET" at 21428.47,13729.6 h69
  text "FILE TYPE:" at 20881.34,13727.08 h69
  text "LANDS" at 12509.23,13667.75 h40
  text "LANDS" at 12509.23,13667.75 h40
  text "ROUTES" at 7382,13606 h75
  text ".Pad_Count" at 12890.23,13583.75 h40
  text ".Pad_Count" at 12890.23,13583.75 h40
  text "PADS" at 12513.23,13581.75 h35
  text "PADS" at 12513.23,13581.75 h35
  text "SUPPLIED ARTWORK/PATTERN MASTER LIST" at 17933,13567.36 h79
  text ".Via_Count" at 12890.23,13501.75 h40
  text ".Via_Count" at 12890.23,13501.75 h40
  text "VIA'S" at 12514.23,13500.75 h35
  text "VIA'S" at 12514.23,13500.75 h35
  text "LAYERS: TOP AND BOTTOM" at 7382,13441 h130
  text "DRAWING No./CAD FILE REF." at 19786,13417.36 h69
  text "REVISION" at 22392.18,13411.87 h69
  text "DESCRIPTION" at 18150,13410.36 h69
  text "PRINT SCALE" at 12506.23,13350.75 h40
  text "PRINT SCALE" at 12506.23,13350.75 h40
  text "MICROSTRIP IMPLEMENTATION" at 7387,13291 h70
  text ".Print_Scale" at 12888.23,13265.75 h40
  text ".Print_Scale" at 12888.23,13265.75 h40
  text "SCALE" at 12511.23,13264.75 h35
  text "SCALE" at 12511.23,13264.75 h35
  text "TRACK = 20mils" at 7387,13146 h70
  text "SPACE = 4mils" at 7387,13026 h70
  text "DIST. FROM GND PLANES = 47.2mils" at 7387,12911 h70
  text "MANUFACTURE DATA" at 13932.98,12799.05 h40
  text "DIFFERENTIAL" at 7397,12641 h70
  text "IMPEDANCE = ~ 107.6 OHMS" at 7397,12521 h70
  text "REFER TO IMPEDANCE NOTE." at 7397,12215 h100
  text "MANUFACTURER" at 13903.88,9722.17 h50
  text "DATE CODE" at 13977.88,9618.17 h50
  text "POLYIMIDE" at 20923.25,9542.89 h69
  text "FR4-01" at 18869.81,9540 h69
  text "FR4-04" at 19578.81,9540 h69
  text "FR4-08" at 20267.81,9540 h69
  text "ARLON" at 21664.81,9540 h69
  text "MATERIAL:" at 17934.39,9532.9 h75
  text "LEGEND" at 14044.88,9523.17 h50
  text "THICKNESS:" at 18425,9353 h69
  text "~0.8mm" at 19291,9353 h69
  text "2.2mm" at 21378,9353 h69
  text "3.2mm" at 22086,9353 h69
  text "TOLERANCE:" at 18386,9175 h69
  text "OTHER +/-" at 21614,9175 h69
  text "WEEK/YEAR" at 13935.88,9074.17 h60
  text "BOW & TWIST:" at 18268,8998 h69
  text "AS SHOWN" at 21614,8998 h69
  text "10.5mmx5.5mm" at 13890.88,8948.17 h50
  text "COPPER THICKNESS (FINISHED)" at 18110,8820 h69
  text "COMPLETE THE DATE CODE" at 13878.88,8819.17 h30
  text "ON THE LEGEND LAYER" at 13919.88,8749.17 h30
  text "WITH DATE OF MANUFACTURE" at 13860.88,8680.17 h30
  text "18um (1/2oz)" at 19291,8644.5 h69
  text "OUTER:" at 18622,8643 h69
  text "70um (2oz)" at 21614,8643 h69
  text "18um (1/2oz)" at 19291,8467.5 h69
  text "INNER SIGNAL:" at 18287,8466 h69
  text "70um (2oz)" at 21614,8466 h69
  text "18um (1/2oz)" at 19291,8291.5 h69
  text "INNER PWR:" at 18405,8290 h69
  text "70um (2oz)" at 21614,8290 h69
  text "STRUCTURE:" at 17953,8093 h75
  text "REFER" at 19291.16,8093 h69
  text "AS PER DRAWING No." at 19291,7916 h69
  text "NOTE:" at 6330,7896 h70
  text "DRILLING:" at 17953,7758 h75
  text "BOARD" at 6187.6,7703.55 h120
  text "VIEWED FROM:" at 18287,7621 h69
  text "SOLDER SIDE" at 20492,7621 h69
  text "CUTOUTS" at 6087.05,7496.55 h120
  text "REFERENCE:" at 18386,7443 h69
  text "PATTERN MASTER LIST" at 20492,7443 h69
  text "DEFINED ON THE" at 6037.85,7352.56 h75
  text "PTH MINIMUM COPPER THICKNESS:" at 18523,7265 h69
  text "OTHER" at 21614,7265 h69
  text "DRILL GUIDE" at 6061.33,7184.03 h140
  text "NPTH:" at 18661,7087 h69
  text "TENTED" at 19291,7087 h69
  text "PADS REMOVED" at 20492,7087 h69
  text "REMOVE PADS" at 21614,7087 h69
  text "LAYER" at 6303.15,7045.56 h75
  text "NONE" at 22121.87,6910.5 h69
  text "2nd DRILL" at 19291,6909 h69
  text "BOTH" at 20492,6909 h69
  text "ARE 1.7MM DIAMETER" at 5938.23,6899.57 h75
  text "ETCHING" at 19291,6693.5 h69
  text "BOARD FINISH:" at 17953,6692 h75
  text "REFER PATTERN MASTER LIST" at 20492,6692 h69
  text "LEGEND / SCREEN PRINT:" at 18523,6514 h69
  text "NONE" at 20197,6514 h69
  text "BUILD CONFIGURATION AND SPECIFICATIONS SUMMARY" at 11296.23,6362.28 h80
  text "COLOUR:" at 18523,6337 h69
  text "YELLOW" at 20492,6337 h69
  text "OTHER" at 21614,6337 h69
  text "PCB MATERIAL SPEC" at 9156.64,6283.04 h80
  text "2 Layer Build" at 11375.13,6192.78 h60
  text "Silk-Screened White Legend" at 13141.13,6192.78 h60
  text "SOLDER RESIST:" at 18209,6141 h69
  text "LIQUID PHOTOIMAGEABLE" at 19291,6141 h69
  text "5 Thou Tracks / 3 Thou Spacing" at 11375.14,6082.78 h60
  text "DO NOT TRIM Legend (Silkscreen)" at 13141.13,6082.78 h60
  text "24 Thou Via / 0.30mm Hole" at 11375.14,5972.78 h60
  text "Board Thickness Approx 1.6mm" at 13141.14,5972.8 h60
  text "MATTE" at 19879.96,5964.36 h69
  text "COLOUR:" at 18523,5963 h69
  text "BLUE" at 21082,5963 h69
  text "G/Y" at 21614,5963 h69
  text "GREEN" at 20487.26,5959.8 h69
  text "r = TYP 4.1" at 9287.98,5951.3 h100
  text "1 Oz Copper Clad" at 11375.13,5862.78 h60
  text "BOARD OUTLINE Layer Denotes Board Cutout" at 13141.13,5862.78 h60
  text "TRACK FINISH:" at 17953,5767 h75
  text "SELECTIVE SOLDER" at 19291,5767 h69
  text "REFLOW SOLDER" at 20846,5767 h69
  text "3um Immersion Gold" at 11375.13,5752.78 h60
  text "Must be BBT (Bare Board Tested)" at 13141.13,5752.78 h60
  text "Standard FR408 Style Material" at 9252.53,5682.37 h60
  text "Gloss Black Solder Mask" at 11375.13,5642.78 h60
  text "Include BBT Certificate with Order" at 13141.13,5642.78 h60
  text "HASL (HOT AIR SOLDER LEVEL)" at 19291.29,5580.26 h69
  text "Dielectric at 1GHz = TYP 4.2" at 9252.53,5572.37 h60
  text "Include All BBT Failed Boards With Order" at 11376.13,5520.78 h60
  text "FR4 Material Construction" at 9252.53,5462.37 h60
  text "REFER PATTERN MASTER LIST" at 19291,5414 h69
  text "OTHER" at 21074.76,5414 h69
  text "288'C Max. Temperature Capability" at 9252.53,5362.37 h60
  text "IPC-4101A /24 Compliant" at 9252.53,5252.37 h60
  text "Tg by DSC ('C) = 180" at 9252.53,5142.37 h60
  text "HARD GOLD PLATE FINISH" at 19291,5039 h69
  text "OTHER" at 20846,5039 h69
  text "94v0/UL94 Compliant" at 9252.53,5032.37 h60
  text "AS SHOWN" at 19291,4862 h69
  text "REFER" at 20846,4862 h69
  text "PROFILING:" at 17953,4664 h75
  text "LAYER STACK CONFIGURATION" at 12210.09,4552.07 h80
  text "REFER PCB BLANK DWG No." at 19291,4488 h69
  text "USE PROFILE/ ROUTE TAPE SUPPLIED" at 19291,4311 h69
  text "(REFER PATTERN MASTER LIST)" at 21121.26,4310.2 h69
  text "2 LAYER BUILD" at 12641.8,4270.07 h80
  text "SQUARE CUT" at 19291,4134.5 h69
  text "V. SCORE" at 21122,4133 h69
  text "BLANK" at 21929,4133 h69
  text "NOTE:" at 9688.88,4039.55 h70
  text "ACCEPTABILITY:" at 17933,3936 h75
  text "MATERIALS AND WORKMANSHIP FOR" at 19094,3936 h69
  text "ALL PRINTED WIRING BOARDS TO MEE" at 20866,3936 h69
  text "T" at 22657,3935 h69
  text "OR EXCEED THE REQUIREMENTS OF:" at 19075,3818 h69
  text "IMPEDANCE" at 9317,3815 h200
  text "TOP LAYER" at 11765.34,3794.35 h30
  text "TL" at 12266.56,3790.85 h30
  text "-  COPPER CLAD" at 13311.33,3788.69 h30
  text "-  CORE" at 13337.09,3735.87 h30
  text "-  COPPER CLAD" at 13311.33,3681.19 h30
  text "BOTTOM LAYER" at 11766.26,3673.87 h30
  text "BL" at 12266.22,3673.87 h30
  text "1" at 21063.5,3660 h69
  text "3" at 21732.5,3660 h69
  text "CONTROLLED LAYERS" at 9291.88,3650.55 h75
  text "LAYERS TOP AND BOTTOM" at 9303,3503 h90
  text "UL CERTIFICATION" at 19290.5,3482 h69
  text "AUSTEL" at 21102.5,3482 h69
  text "A" at 20433.58,3305.67 h69
  text "B" at 20748.58,3305.67 h69
  text "MIL-P-55110E GRP" at 19290.5,3305 h69
  text "AS2546" at 21096.9,3305 h69
  text "OTHER" at 21889.9,3305 h69
  text "IMPEDANCE =" at 9501,3197 h70
  text "ADDITIONAL REQUIREMENTS:" at 17930,3145 h75
  text "100 OHMS +/- 10%" at 9327,3060 h70
  text "MICROSECTION:" at 18189,3010 h69
  text "SAMPLE PLAN" at 19822.76,3010 h69
  text "MIL-P-55110E SERIAL Nos. PER ORDER" at 20846.45,3010 h69
  text "MIL-P-55110E GRP" at 19822,2832.56 h69
  text "A" at 20965.08,2833.23 h69
  text "B" at 21280.08,2833.23 h69
  text "CERTIFICATION:" at 18189,2832 h69
  text "NONE" at 19290.5,2832 h69
  text "IPC CLASS:" at 21436,2832 h69
  text "1" at 22205,2832 h69
  text "3" at 22874,2832 h69
  text "TOTAL BOARD THICKNESS: APPROX" at 12115.25,2744.87 h30
  text "1.2mm" at 12949.25,2744.86 h30
  text "(47.244mil)" at 13123.95,2745.47 h30
  text "ADJUST DIELECTRIC THICKNESS" at 9317,2737 h50
  text "QUALITY RELEASE REPORT" at 19822,2654 h69
  text "TO MEET SPECIFIED IMPEDANCE" at 9313,2633 h50
  text "ELECTRICAL TEST: Bare Board" at 18189,2477 h66.93
  text "NONE" at 19822,2477 h69
  text "PER ORDER" at 21633,2477 h69
  text "MIN. PITCH" at 21634,2300.17 h69
  text "SURFACE MOUNT:" at 18189,2299 h69
  text "NONE" at 19822,2299 h69
  text "1 SIDE" at 20385.96,2296.86 h69
  text "MANUFACTURER'S ID/LOGO:" at 18189,2123 h69
  text "NONE" at 19822,2123 h69
  text "FOIL" at 20412.31,2123 h69
  text "REFER" at 21634,2123 h69
  text "NONE" at 21438,1945 h69
  text "MANUFACTURER'S ACCREDITATION:" at 18189,1925 h69
  text "PACKAGING AND HANDLING:" at 18189,1749 h69
  text "REFER" at 20841,1749 h69
Mechanical 7:
  drawing of 1016 lines, arcs and shapes, not listed
  text "1" at 2126,16181 h118
  text "2" at 4960,16181 h118
  text "3" at 7795,16181 h118
  text "4" at 10511,16181 h118
  text "5" at 13346,16181 h118
  text "6" at 16102,16181 h118
  text "7" at 18937,16181 h118
  text "8" at 21850,16181 h118
  text "NANOBOARD" at 1660,15683 h120
  text "DT01.02" at 4818.75,15679.48 h140
  text "A" at 826,14921 h118
  text "A" at 23031,14921 h118
  text "IDENTIFICATION DATA" at 13932.98,12681.05 h40
  text "B" at 846,12166 h118
  text "B" at 23051,12166 h118
  text "C" at 846,9606 h118
  text "C" at 23051,9606 h118
  text "D" at 846,6890 h118
  text "D" at 23051,6890 h118
  text "mm" at 591,6496 h79 r90
  text "E" at 846,4232 h118
  text "E" at 23051,4232 h118
  text "0" at 591,2441 h79 r90
  text "DO NOT" at 217,1890 h79
  text "SCALE" at 236,1752 h79
  text "DIMENSIONS" at 98,1555 h79
  text "F" at 846,1516 h118
  text "F" at 23051,1516 h118
  text "SCALE:" at 21376.7,1457.08 h70
  text "ALTIUM LIMITED" at 15308.95,1440.88 h70
  text "DESIGNER" at 14414.66,1438.71 h70
  text "DATE" at 16887.86,1434.08 h70
  text "LEVEL 3 / 12A RODBOROUGH ROAD" at 18204.55,1429.54 h62.99
  text "IN" at 354,1417 h79
  text "FRENCHS FOREST - SYDNEY 2086" at 18202.77,1335.16 h62.99
  text ".Print_Scale" at 21772.96,1282.87 h100
  text "MILLIMETRES" at 79,1260 h79
  text "NSW AUSTRALIA" at 18203.95,1247.12 h62.99
  text "DRAWN" at 14412.86,1241.08 h70
  text "08.SEPT.07" at 16785.96,1236.87 h70
  text "Steven. R. Howell" at 15307.66,1235.71 h70
  text "DATE:" at 21373.7,1063.37 h70
  text "01.APR.08" at 13793.91,1052.03 h70
  text "UPDATED WITH HOT PLUG CAPABILITY" at 7977.85,1050.85 h70
  text "S.HOWELL" at 13214.84,1048.84 h70
  text "2" at 7486.86,1046.83 h70
  text "CHECKED" at 14412.86,1047.08 h70
  text "Steven. R. Howell" at 15301.96,1042.87 h70
  text "INDEX" at 17555.96,1042.87 h70
  text "08.SEPT.07" at 16785.96,1036.87 h70
  text ".Print_Date" at 21742.96,907.87 h100
  text "08.SEPT.07" at 13793.91,854.03 h70
  text "DESIGN CREATED" at 7977.85,852.85 h70
  text "S.HOWELL" at 13214.84,850.84 h70
  text "1" at 7486.86,848.83 h70
  text "ALTIUM DEVELOPMENT PRODUCTS" at 15655.96,848.87 h70
  text "CUSTOMER" at 14410.96,839.87 h70
  text "Title:" at 17558.86,835.78 h80
  text "SHEET" at 21377.17,669.67 h70
  text "DT01.01 - DEVELOPMENT TOOL 01.02" at 17572.97,662.85 h90
  text "REVISION" at 7337.84,651.84 h70
  text "DESCRIPTION OF TASK OR MODIFICATION" at 10159.84,651.84 h70
  text "DATE" at 13896.73,632.67 h70
  text "APPD" at 13306.18,630.42 h70
  text "A2" at 22728.86,544.08 h78.74
  text ".Pcb_File_Name" at 9629.96,463.9 h70
  text ".Printout_Name" at 8024.96,448.87 h70
  text "TEMPLATE: -" at 7337.84,446.84 h70
  text "1" at 2126,236 h118
  text "2" at 4960,236 h118
  text "3" at 7795,236 h118
  text "4" at 10511,236 h118
  text "5" at 13346,236 h118
  text "6" at 16102,236 h118
  text "7" at 18937,236 h118
  text "8" at 21850,236 h118
Mechanical 15:
  rectangle: 13672.98,12536.05 13862.98,12631.05
  lines w5: 13672.98,12536.05 13672.98,12631.05 14592.98,12631.05 14592.98,12536.05 13672.98,12536.05
  text "DIMENSIONS" at 13932.98,12563.05 h40
Drill Drawing:
  rectangle: 13672.98,13244.05 13862.98,13339.05
  lines w0.39: 10508.24,8378.48 cw(c10508.24,8516.27) 10508.24,8654.07 10738.55,8654.07 cw(c10738.55,8634.38) 10758.24,8634.38 10758.24,8601.11 10758.24,8398.16 cw(c10738.55,8398.16) 10738.55,8378.48 10508.24,8378.48 ; 10508.24,10032.02 cw(c10508.24,10169.82) 10508.24,10307.61 10738.55,10307.61 cw(c10738.55,10287.93) 10758.24,10287.93 10758.24,10084.97 10758.24,10051.71 cw(c10738.55,10051.71) 10738.55,10032.02 10508.24,10032.02
  lines w5: 9328.42,9182.61 ccw(c11116.51,9343.04) 9388.86,8854.97 ccw(c10303.51,10107.8) 9633.7,8708.68 cw(c9616.7,8673.17) 9654.65,8662.69 9631.51,8578.94 ccw(c11007.41,11111.18) 10303.15,8316.66 10312.86,8356.21 cw(c10339.63,8349.64) 10366.39,8343.07 10356.73,8303.7 ccw(c11007.41,11111.18) 11097.83,8230.7 11044.32,8363.83 cw(c11080.85,8378.51) 11080.68,8417.88 ccw(c11063.75,12502.73) 11376.58,8429.84 ccw(c8605.87,9343.04) 11463.13,8754.11 11463.13,9931.98 ccw(c8605.87,9343.04) 11376.58,10256.24 ccw(c11063.75,6183.36) 11080.68,10268.2 cw(c11080.85,10307.57) 11044.32,10322.26 11097.83,10455.38 ccw(c11007.41,7574.91) 10356.73,10382.38 10366.39,10343.02 cw(c10339.63,10336.45) 10312.86,10329.88 10303.15,10369.43 ccw(c11007.41,7574.91) 9631.51,10107.14 9654.65,10023.4 cw(c9616.7,10012.92) 9633.7,9977.41 ccw(c10303.51,8578.29) 9388.86,9831.12 ccw(c11116.51,9343.04) 9328.42,9503.48 9636.2,9503.48 cw(c9636.2,9483.79) 9655.89,9483.79 9655.89,9202.3 cw(c9636.2,9202.3) 9636.2,9182.61 9328.42,9182.61 ; 13672.98,13244.05 13672.98,13339.05 14592.98,13339.05 14592.98,13244.05 13672.98,13244.05
  text "DRILL DRAWING" at 13932.98,13271.05 h40
  text ".Legend" at 1120.03,501.08 h68.9

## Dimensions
11376.58,8429.84 to 11097.83,10455.38 on Mechanical 1
11463.13,9931.98 to 9328.42,9503.48 on Mechanical 1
